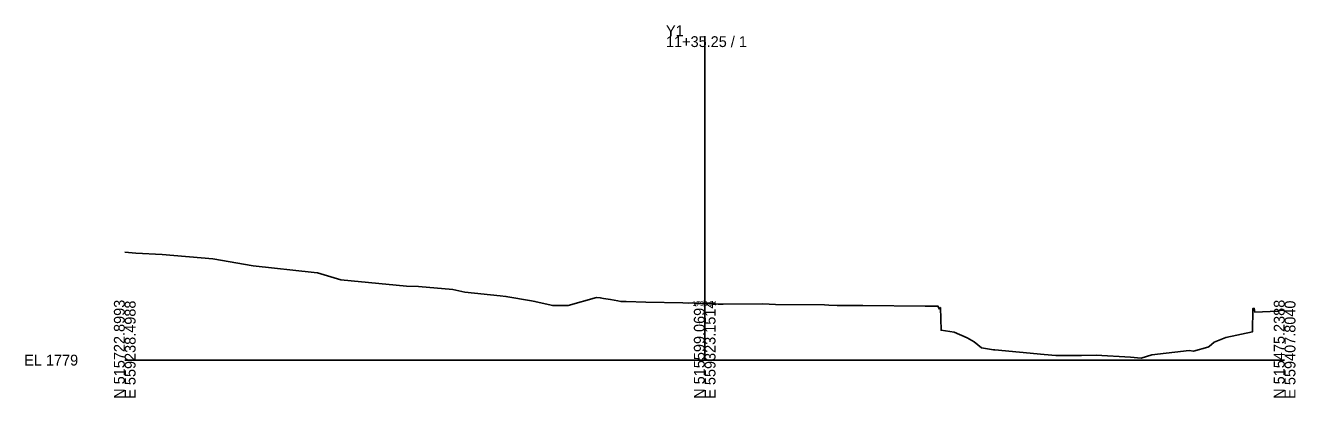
# Model space of a CAD drawing. Extents: x -26 to 303, y 990 to 1587.
# Drawn here: x -25.7 to 302.8, y 1490.3 to 1586.6 of the extents above; entities that cross this region are included whole.
import ezdxf

# ---------------------------------------------------------------- set-up
doc = ezdxf.new("R2010")
doc.units = 0
for name, color, linetype in [('Exist Cross Section Cell', 7, 'Continuous'), ('Exist XS Center Line Elevation Label', 7, 'Continuous'), ('Exist XS Ground Line', 7, 'Continuous')]:
    doc.layers.add(name, color=color, linetype=linetype)

msp = doc.modelspace()

# ---------------------------------------------------------------- linework, layer by layer
at = {"layer": 'Exist Cross Section Cell'}
for p, q in [((150, 1500), (150, 1583.77)), ((0, 1500), (150, 1500)), ((150, 1500), (300, 1500))]:
    msp.add_line(p, q, dxfattribs=at)
at = {"layer": 'Exist XS Ground Line'}
msp.add_lwpolyline([(0, 1527.92), (2.85, 1527.66), (9.64, 1527.35), (22.75, 1526.21), (33.22, 1524.35), (48.99, 1522.7), (49.89, 1522.54), (55.93, 1520.76), (72.9, 1519.12), (75.96, 1519.06), (84.82, 1518.29), (87.99, 1517.55), (97.08, 1516.64), (98.58, 1516.47), (105.25, 1515.29), (105.64, 1515.25), (106.11, 1515.19), (109.55, 1514.38), (110.71, 1514.1), (114.66, 1514.12), (121.99, 1516.2), (122.98, 1516.11), (123.85, 1515.96), (125.64, 1515.7), (127.57, 1515.33), (128.28, 1515.19), (129.68, 1515.18), (134.79, 1515.01), (144.39, 1514.79), (145.92, 1514.77), (146.76, 1514.78), (150, 1514.64), (151.71, 1514.56), (152.39, 1514.55), (153.51, 1514.51), (153.96, 1514.5), (154.32, 1514.49), (154.79, 1514.47), (165.03, 1514.56), (168.35, 1514.4), (180.97, 1514.26), (182.13, 1514.2), (184.23, 1514.14), (187.71, 1514.11), (190.91, 1514.1), (207.02, 1513.95), (210.42, 1513.95), (210.43, 1513.76), (210.75, 1513.19), (210.76, 1513.47), (210.97, 1513.58), (211.15, 1507.73), (214.54, 1507.21), (217.93, 1505.75), (219.67, 1504.69), (221.6, 1503.14), (224.69, 1502.68), (225.06, 1502.65), (237.79, 1501.43), (240.79, 1501.16), (247.45, 1501.23), (251.27, 1501.26), (260.1, 1500.73), (262.88, 1500.51), (265.68, 1501.35), (275.28, 1502.48), (276.44, 1502.31), (280.13, 1503.36), (280.49, 1503.5), (281.74, 1504.66), (284.76, 1505.83), (291.69, 1507.29), (291.76, 1513.32), (291.97, 1513.32), (292.16, 1513.39), (292.29, 1512.44), (298.25, 1512.68), (298.76, 1512.82), (300, 1512.92)], dxfattribs=at)
msp.add_lwpolyline([(0, 1527.92), (2.85, 1527.66), (9.64, 1527.35), (22.75, 1526.21), (33.22, 1524.35), (48.99, 1522.7), (49.89, 1522.54), (55.93, 1520.76), (72.9, 1519.12), (75.96, 1519.06), (84.82, 1518.29), (87.99, 1517.55), (97.08, 1516.64), (98.58, 1516.47), (105.25, 1515.29), (105.64, 1515.25), (106.11, 1515.19), (109.55, 1514.38), (110.71, 1514.1), (114.66, 1514.12), (121.99, 1516.2), (122.98, 1516.11), (123.85, 1515.96), (125.64, 1515.7), (127.57, 1515.33), (128.28, 1515.19), (129.68, 1515.18), (134.79, 1515.01), (144.39, 1514.79), (145.92, 1514.77), (146.76, 1514.78), (150, 1514.64), (151.71, 1514.56), (152.39, 1514.55), (153.51, 1514.51), (153.96, 1514.5), (154.32, 1514.49), (154.79, 1514.47), (165.03, 1514.56), (168.35, 1514.4), (180.97, 1514.26), (182.13, 1514.2), (184.23, 1514.14), (187.71, 1514.11), (190.91, 1514.1), (207.02, 1513.95), (210.42, 1513.95), (210.43, 1513.76), (210.75, 1513.19), (210.76, 1513.47), (210.97, 1513.58), (211.15, 1507.73), (214.54, 1507.21), (217.93, 1505.75), (219.67, 1504.69), (221.6, 1503.14), (224.69, 1502.68), (225.06, 1502.65), (237.79, 1501.43), (240.79, 1501.16), (247.45, 1501.23), (251.27, 1501.26), (260.1, 1500.73), (262.88, 1500.51), (265.68, 1501.35), (275.28, 1502.48), (276.44, 1502.31), (280.13, 1503.36), (280.49, 1503.5), (281.74, 1504.66), (284.76, 1505.83), (291.69, 1507.29), (291.76, 1513.32), (291.97, 1513.32), (292.16, 1513.39), (292.29, 1512.44), (298.25, 1512.68), (298.76, 1512.82), (300, 1512.92)], dxfattribs=at)

# ---------------------------------------------------------------- texts
at = {"layer": 'Exist Cross Section Cell'}
for s, p in [('Y1', (140, 1583.77)), ('11+35.25 / 1', (140, 1580.97)), ('EL 1779', (-26, 1498.6))]:
    msp.add_text(s, height=2.8, dxfattribs=at).set_placement(p)
for s, p in [('N 515722.8993', (0, 1490)), ('E 559238.4988', (2.8, 1490)), ('N 515599.0691', (150, 1490)), ('E 559323.1514', (152.8, 1490)), ('N 515475.2388', (300, 1490)), ('E 559407.8040', (302.8, 1490))]:
    msp.add_text(s, height=2.8, rotation=90, dxfattribs=at).set_placement(p)
at = {"layer": 'Exist XS Center Line Elevation Label'}
msp.add_text('1793.64', height=1.25, dxfattribs=at).set_placement((146.86, 1514.01))
msp.add_text('1793.64', height=1.25, dxfattribs=at).set_placement((146.86, 1514.01))

doc.saveas('drawing.dxf')
